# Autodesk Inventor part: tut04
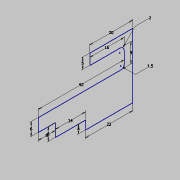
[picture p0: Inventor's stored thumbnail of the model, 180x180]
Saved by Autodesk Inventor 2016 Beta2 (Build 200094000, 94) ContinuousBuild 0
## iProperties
Created: 2015-02
Part Number: tut04
Material: Generic
Document SubType Name: Modeling
Designer: Sandeep
Density: 1 g/cm^3
Appearance: Default
Author: Sandeep
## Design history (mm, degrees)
sketch "Sketch1"
  geometry: L1 (0, 0)-(-22, 0); L2 (-22, 0)-(-22, 4); L3 (-22, 4)-(-36, 4); L4 (-36, 4)-(-36, 10); L5 (-36, 10)-(-44, 10); L6 (-44, 10)-(-44, 16); L7 (-44, 16)-(-5.5, 16); L8 (-4, 17.5)-(-4, 23); L9 (-6, 25)-(-20, 25); L10 (-20, 25)-(-20, 30); L11 (-20, 30)-(0, 30); L12 (0, 30)-(0, 0); A1 r 2 centre (-6, 23) between (-4, 23) and (-6, 25); A2 r 1.5 centre (-5.5, 17.5) between (-5.5, 16) and (-4, 17.5); 2 further points
  constraints: 24 end point, 9 perpendicular, 4 point on circle, 4 point on line, 4 tangent, 2 centre point, 2 horizontal
  dimensions: "d0" = 22 distance of L1.start L1.end; "d1" = 4 distance of L1.end L2.end; "d2" = 14 distance of L2.end L3.end; "d3" = 6 distance of L3.end L4.end; "d4" = 8 distance of L4.end L5.end; "d5" = 6 distance of L5.end L6.end; "d6" = 40 distance of L6.end point (-4, 16); "d7" = 9 distance of point (-4, 16) point (-4, 25); "d8" = 16 distance of point (-4, 25) L9.end; "d9" = 5 distance of L9.end L10.end; "d10" = 20 distance of L10.end L11.end; "d11" = 2 radius of A1; "d12" = 1.5 radius of A2
